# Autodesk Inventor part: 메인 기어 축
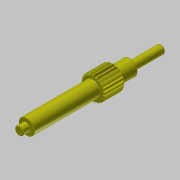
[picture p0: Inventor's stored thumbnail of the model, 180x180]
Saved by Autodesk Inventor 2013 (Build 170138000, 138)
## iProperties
Created: 2018-12
Part Number: 메인 기어 축
Material: 강철, 연강
Document SubType Name: Modeling
Designer: mduedu
Categories: <?xml version="1.0" encoding="UTF-16"?> <MemberInstance><Categories><FamilyTemplate><FamilyTemplateParameter ValueType="xs:double" Id="1" ObjectReferenceKey="da
Density: 1 g/cm^3
CustomPartVersion: 1
Author: mduedu
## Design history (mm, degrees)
sketch "Sketch1"
  geometry: C1 r 11.3 at (0, 0)
  constraints: 1 centre point
  dimensions: "d0" = 22.6 diameter of C1 (= da_da)
extrude "Extrusion1" new body sketch "Sketch1" distance "d1" = 20 (= da_b); taper "d2" = 0 deg
workplane "Work Plane2"
sketch "Sketch2"
  geometry: C1 r 11.3 at (0, 0) reference; C2 r 10.5 at (0, 0)
  constraints: 1 centre point, 1 coincident
  dimensions: "d3" = 21 diameter of C2 (= da_dw)
feature "피치 지름" sketch "Sketch2" dims "d4" = 10, "d5" = 0
workplane "Work Plane8"
workplane "Work Plane9"
chamfer "모따기1" distance "d49" = 1; stored, may be unused: second distance "d50" = 2, angle "d51" = 45 deg
sketch "스케치3"
  geometry: C1 r 7.5 at (0, 0); 1 further point
  constraints: 1 centre point, 1 coincident
  dimensions: "d52" = 15 diameter of C1
extrude "돌출2" join sketch "스케치3" distance "d53" = 64; taper "d54" = 0 deg
sketch "스케치4"
  geometry: C1 r 4 at (0, 0); 1 further point
  constraints: 1 centre point, 1 coincident
  dimensions: "d55" = 8 diameter of C1
extrude "돌출3" join sketch "스케치4" distance "d56" = 7; taper "d57" = 0 deg
sketch "스케치5"
  geometry: C1 r 7.5 at (0, 0) reference; C2 r 7.5 at (0, 0) reference; 1 further point
extrude "돌출4" join sketch "스케치5" distance "d58" = 16; taper "d59" = 0 deg
sketch "스케치6"
  geometry: C1 r 4 at (0, 0); 1 further point
  constraints: 1 centre point, 1 coincident
  dimensions: "d60" = 8 diameter of C1
extrude "돌출5" join sketch "스케치6" distance "d61" = 30; taper "d62" = 0 deg
chamfer "모따기2" distance "d63" = 0.5; stored, may be unused: second distance "d64" = 2, angle "d65" = 45 deg
fillet "모깎기1" dims "d66" = 0.5
feature "스퍼 기어" dims "da_b" = 20, "da_d" = 21, "da_aw" = 31, "da_da" = 22.6, "da_df" = 19.086, "da_dw" = 21, angle "da_beta" = 0 deg, "da_lefttooth" = 0, "da_righttooth" = 0
sketch "스케치7" dims "d67" = 18
  geometry: C1 r 0.25 at (0, -9); 2 further points
  constraints: 2 vertical alignment, 1 centre point, 1 coincident, 2 other
  dimensions: "d68" = 0.5 diameter of C1
extrude "돌출6" join sketch "스케치7" distance "d69" = 0.3; taper "d70" = 0 deg
body "Solid1"
body "Srf1"
node "투영된 루프1"
other parameters: "d16" = 31 (= da_aw), "d17" = 0, "d34" = 1.496 (computed from da_z), "d39" = 0, "d41" = 0, "d43" = 31 (= da_aw), "d46" = 31 (= da_aw), "d47" = 0, "d48" = 0
